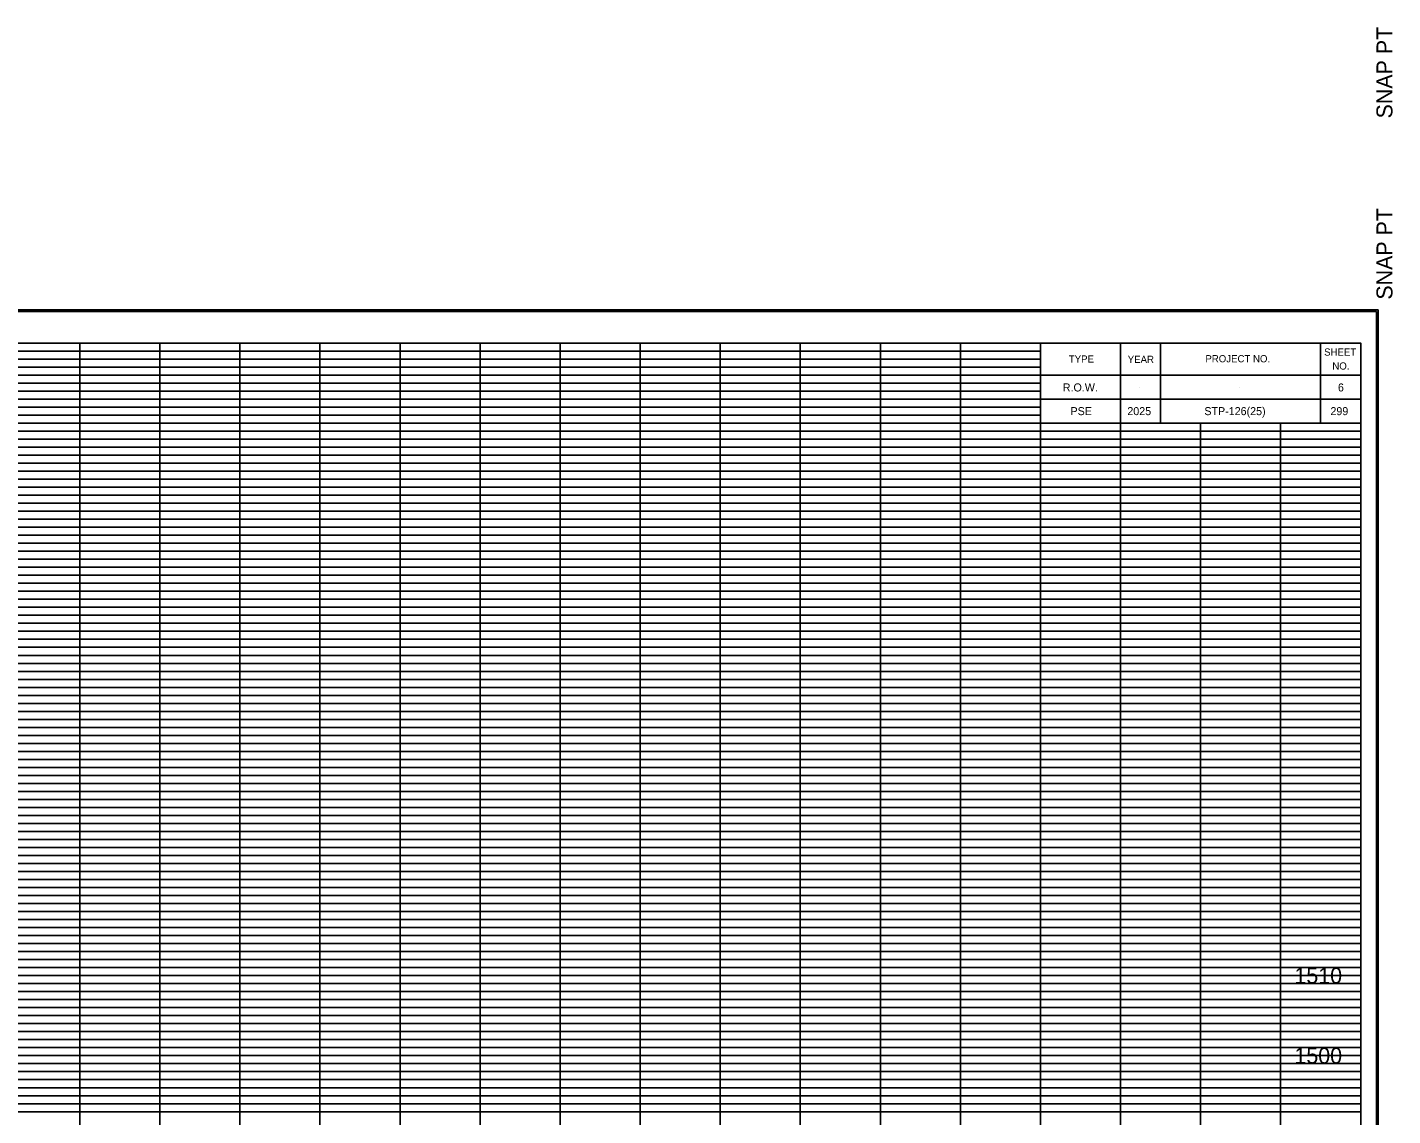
# Model space of a CAD drawing. Extents: x 980 to 2064, y 978 to 2267.
# Drawn here: x 1523.4 to 1694, y 1113.5 to 1249.4 of the extents above; entities that cross this region are included whole.
import ezdxf

# ---------------------------------------------------------------- set-up
doc = ezdxf.new("R2010")
doc.units = 0
for name, color, linetype in [('Default', 7, 'Continuous'), ('DESIGN - SCRATCH - User 1', 7, 'Continuous'), ('DESIGN - SHEET - Corner Text', 7, 'Continuous'), ('DESIGN - SHEET - Light Grid', 7, 'Continuous'), ('DESIGN - SHEET - Linework', 7, 'Continuous'), ('DESIGN - SHEET - Plot Shape', 7, 'Continuous')]:
    doc.layers.add(name, color=color, linetype=linetype)

# ---------------------------------------------------------------- blocks, each defined once
blk = doc.blocks.new('XSTSHT')
at = {"layer": 'DESIGN - SCRATCH - User 1'}
for p, q in [((28.5, 20.45), (28.5, 20.45)), ((29.24, 20.45), (29.24, 20.45)), ((30.49, 20.45), (30.49, 20.45)), ((31.74, 20.45), (31.74, 20.45)), ((28.5, 20.15), (28.5, 20.15)), ((29.24, 20.15), (29.24, 20.15)), ((30.49, 20.15), (30.49, 20.15)), ((31.74, 20.15), (31.74, 20.15))]:
    blk.add_line(p, q, dxfattribs=at)
at = {"layer": 'DESIGN - SHEET - Light Grid'}
for p, q in [((8, 20.9), (16, 20.9)), ((16, 20.9), (24, 20.9)), ((24, 20.9), (28, 20.9)), ((8, 20.8), (16, 20.8)), ((8, 20.7), (16, 20.7)), ((16, 20.8), (24, 20.8)), ((16, 20.7), (24, 20.7)), ((24, 20.8), (28, 20.8)), ((24, 20.7), (28, 20.7)), ((8, 20.6), (16, 20.6)), ((8, 20.5), (16, 20.5)), ((16, 20.6), (24, 20.6)), ((16, 20.5), (24, 20.5)), ((24, 20.6), (28, 20.6)), ((24, 20.5), (28, 20.5)), ((8, 20.4), (16, 20.4)), ((8, 20.3), (16, 20.3)), ((16, 20.4), (24, 20.4)), ((16, 20.3), (24, 20.3)), ((24, 20.4), (28, 20.4)), ((24, 20.3), (28, 20.3)), ((8, 20.2), (16, 20.2)), ((16, 20.2), (24, 20.2)), ((24, 20.2), (28, 20.2)), ((8, 20.1), (16, 20.1)), ((16, 20.1), (24, 20.1)), ((24, 20.1), (28, 20.1)), ((8, 19.9), (16, 19.9)), ((8, 19.8), (16, 19.8)), ((16, 19.9), (24, 19.9)), ((16, 19.8), (24, 19.8)), ((24, 19.9), (32, 19.9)), ((24, 19.8), (32, 19.8)), ((8, 19.7), (16, 19.7)), ((16, 19.7), (24, 19.7)), ((24, 19.7), (32, 19.7)), ((8, 19.6), (16, 19.6)), ((8, 19.5), (16, 19.5)), ((16, 19.6), (24, 19.6)), ((16, 19.5), (24, 19.5)), ((24, 19.6), (32, 19.6)), ((24, 19.5), (32, 19.5)), ((8, 19.4), (16, 19.4)), ((8, 19.3), (16, 19.3)), ((16, 19.4), (24, 19.4)), ((16, 19.3), (24, 19.3)), ((24, 19.4), (32, 19.4)), ((24, 19.3), (32, 19.3)), ((8, 19.2), (16, 19.2)), ((16, 19.2), (24, 19.2)), ((24, 19.2), (32, 19.2)), ((8, 19.1), (16, 19.1)), ((16, 19.1), (24, 19.1)), ((24, 19.1), (32, 19.1)), ((8, 18.9), (16, 18.9)), ((8, 18.8), (16, 18.8)), ((16, 18.9), (24, 18.9)), ((16, 18.8), (24, 18.8)), ((24, 18.9), (32, 18.9)), ((24, 18.8), (32, 18.8)), ((8, 18.7), (16, 18.7)), ((8, 18.6), (16, 18.6)), ((16, 18.7), (24, 18.7)), ((16, 18.6), (24, 18.6)), ((24, 18.7), (32, 18.7)), ((24, 18.6), (32, 18.6)), ((8, 18.5), (16, 18.5)), ((16, 18.5), (24, 18.5)), ((24, 18.5), (32, 18.5)), ((8, 18.4), (16, 18.4)), ((8, 18.3), (16, 18.3)), ((16, 18.4), (24, 18.4)), ((16, 18.3), (24, 18.3)), ((24, 18.4), (32, 18.4)), ((24, 18.3), (32, 18.3)), ((8, 18.2), (16, 18.2)), ((8, 18.1), (16, 18.1)), ((16, 18.2), (24, 18.2)), ((16, 18.1), (24, 18.1)), ((24, 18.2), (32, 18.2)), ((24, 18.1), (32, 18.1)), ((8, 17.9), (16, 17.9)), ((8, 17.8), (16, 17.8)), ((16, 17.9), (24, 17.9)), ((16, 17.8), (24, 17.8)), ((24, 17.9), (32, 17.9)), ((24, 17.8), (32, 17.8)), ((8, 17.7), (16, 17.7)), ((8, 17.6), (16, 17.6)), ((16, 17.7), (24, 17.7)), ((16, 17.6), (24, 17.6)), ((24, 17.7), (32, 17.7)), ((24, 17.6), (32, 17.6)), ((8, 17.5), (16, 17.5)), ((8, 17.4), (16, 17.4)), ((16, 17.5), (24, 17.5)), ((16, 17.4), (24, 17.4)), ((24, 17.5), (32, 17.5)), ((24, 17.4), (32, 17.4)), ((8, 17.3), (16, 17.3)), ((16, 17.3), (24, 17.3)), ((24, 17.3), (32, 17.3)), ((8, 17.2), (16, 17.2)), ((8, 17.1), (16, 17.1)), ((16, 17.2), (24, 17.2)), ((16, 17.1), (24, 17.1)), ((24, 17.2), (32, 17.2)), ((24, 17.1), (32, 17.1)), ((8, 16.9), (16, 16.9)), ((16, 16.9), (24, 16.9)), ((24, 16.9), (32, 16.9)), ((8, 16.8), (16, 16.8)), ((16, 16.8), (24, 16.8)), ((24, 16.8), (32, 16.8)), ((8, 16.7), (16, 16.7)), ((8, 16.6), (16, 16.6)), ((16, 16.7), (24, 16.7)), ((16, 16.6), (24, 16.6)), ((24, 16.7), (32, 16.7)), ((24, 16.6), (32, 16.6)), ((8, 16.5), (16, 16.5)), ((8, 16.4), (16, 16.4)), ((16, 16.5), (24, 16.5)), ((16, 16.4), (24, 16.4)), ((24, 16.5), (32, 16.5)), ((24, 16.4), (32, 16.4)), ((8, 16.3), (16, 16.3)), ((16, 16.3), (24, 16.3)), ((24, 16.3), (32, 16.3)), ((8, 16.2), (16, 16.2)), ((8, 16.1), (16, 16.1)), ((16, 16.2), (24, 16.2)), ((16, 16.1), (24, 16.1)), ((24, 16.2), (32, 16.2)), ((24, 16.1), (32, 16.1)), ((8, 15.9), (16, 15.9)), ((16, 15.9), (24, 15.9)), ((24, 15.9), (32, 15.9)), ((8, 15.8), (16, 15.8)), ((8, 15.7), (16, 15.7)), ((16, 15.8), (24, 15.8)), ((16, 15.7), (24, 15.7)), ((24, 15.8), (32, 15.8)), ((24, 15.7), (32, 15.7)), ((8, 15.6), (16, 15.6)), ((16, 15.6), (24, 15.6)), ((24, 15.6), (32, 15.6)), ((8, 15.5), (16, 15.5)), ((8, 15.4), (16, 15.4)), ((16, 15.5), (24, 15.5)), ((16, 15.4), (24, 15.4)), ((24, 15.5), (32, 15.5)), ((24, 15.4), (32, 15.4)), ((8, 15.3), (16, 15.3)), ((8, 15.2), (16, 15.2)), ((16, 15.3), (24, 15.3)), ((16, 15.2), (24, 15.2)), ((24, 15.3), (32, 15.3)), ((24, 15.2), (32, 15.2)), ((8, 15.1), (16, 15.1)), ((16, 15.1), (24, 15.1)), ((24, 15.1), (32, 15.1)), ((8, 14.9), (16, 14.9)), ((16, 14.9), (24, 14.9)), ((24, 14.9), (32, 14.9)), ((8, 14.8), (16, 14.8)), ((8, 14.7), (16, 14.7)), ((16, 14.8), (24, 14.8)), ((16, 14.7), (24, 14.7)), ((24, 14.8), (32, 14.8)), ((24, 14.7), (32, 14.7)), ((8, 14.6), (16, 14.6)), ((8, 14.5), (16, 14.5)), ((16, 14.6), (24, 14.6)), ((16, 14.5), (24, 14.5)), ((24, 14.6), (32, 14.6)), ((24, 14.5), (32, 14.5)), ((8, 14.4), (16, 14.4)), ((16, 14.4), (24, 14.4)), ((24, 14.4), (32, 14.4)), ((8, 14.3), (16, 14.3)), ((8, 14.2), (16, 14.2)), ((16, 14.3), (24, 14.3)), ((16, 14.2), (24, 14.2)), ((24, 14.3), (32, 14.3)), ((24, 14.2), (32, 14.2)), ((8, 14.1), (16, 14.1)), ((16, 14.1), (24, 14.1)), ((24, 14.1), (32, 14.1)), ((8, 13.9), (16, 13.9)), ((16, 13.9), (24, 13.9)), ((24, 13.9), (32, 13.9)), ((8, 13.8), (16, 13.8)), ((8, 13.7), (16, 13.7)), ((16, 13.8), (24, 13.8)), ((16, 13.7), (24, 13.7)), ((24, 13.8), (32, 13.8)), ((24, 13.7), (32, 13.7)), ((8, 13.6), (16, 13.6)), ((8, 13.5), (16, 13.5)), ((16, 13.6), (24, 13.6)), ((16, 13.5), (24, 13.5)), ((24, 13.6), (32, 13.6)), ((24, 13.5), (32, 13.5)), ((8, 13.4), (16, 13.4)), ((16, 13.4), (24, 13.4)), ((24, 13.4), (32, 13.4)), ((8, 13.3), (16, 13.3)), ((8, 13.2), (16, 13.2)), ((16, 13.3), (24, 13.3)), ((16, 13.2), (24, 13.2)), ((24, 13.3), (32, 13.3)), ((24, 13.2), (32, 13.2)), ((8, 13.1), (16, 13.1)), ((16, 13.1), (24, 13.1)), ((24, 13.1), (32, 13.1)), ((8, 12.9), (16, 12.9)), ((8, 12.8), (16, 12.8)), ((16, 12.9), (24, 12.9)), ((16, 12.8), (24, 12.8)), ((24, 12.9), (32, 12.9)), ((24, 12.8), (32, 12.8)), ((8, 12.7), (16, 12.7)), ((16, 12.7), (24, 12.7)), ((24, 12.7), (32, 12.7)), ((8, 12.6), (16, 12.6)), ((8, 12.5), (16, 12.5)), ((16, 12.6), (24, 12.6)), ((16, 12.5), (24, 12.5)), ((24, 12.6), (32, 12.6)), ((24, 12.5), (32, 12.5)), ((8, 12.4), (16, 12.4)), ((8, 12.3), (16, 12.3)), ((16, 12.4), (24, 12.4)), ((16, 12.3), (24, 12.3)), ((24, 12.4), (32, 12.4)), ((24, 12.3), (32, 12.3)), ((8, 12.2), (16, 12.2)), ((16, 12.2), (24, 12.2)), ((24, 12.2), (32, 12.2)), ((8, 12.1), (16, 12.1)), ((16, 12.1), (24, 12.1)), ((24, 12.1), (32, 12.1)), ((8, 11.9), (16, 11.9)), ((8, 11.8), (16, 11.8)), ((16, 11.9), (24, 11.9)), ((16, 11.8), (24, 11.8)), ((24, 11.9), (32, 11.9)), ((24, 11.8), (32, 11.8)), ((8, 11.7), (16, 11.7)), ((8, 11.6), (16, 11.6)), ((16, 11.7), (24, 11.7)), ((16, 11.6), (24, 11.6)), ((24, 11.7), (32, 11.7)), ((24, 11.6), (32, 11.6)), ((8, 11.5), (16, 11.5)), ((16, 11.5), (24, 11.5)), ((24, 11.5), (32, 11.5)), ((8, 11.4), (16, 11.4)), ((16, 11.4), (24, 11.4)), ((24, 11.4), (32, 11.4))]:
    blk.add_line(p, q, dxfattribs=at)
at = {"layer": 'DESIGN - SHEET - Linework'}
for p, q in [((-1.823, 21.414), (32.217, 21.414)), ((32.217, 21.414), (32.217, -0.414)), ((16, 0), (16, 21)), ((17, 0), (17, 21)), ((18, 0), (18, 21)), ((19, 0), (19, 21)), ((20, 0), (20, 21)), ((21, 0), (21, 21)), ((22, 0), (22, 21)), ((23, 0), (23, 21)), ((24, 0), (24, 21)), ((25, 0), (25, 21)), ((26, 0), (26, 21)), ((27, 0), (27, 21)), ((0, 20), (28, 20)), ((28, 0), (28, 20)), ((29, 0), (29, 20)), ((30, 0), (30, 20)), ((31, 0), (31, 20)), ((0, 19), (32, 19)), ((0, 18), (32, 18)), ((0, 17), (32, 17)), ((0, 16), (32, 16)), ((0, 15), (32, 15)), ((0, 14), (32, 14)), ((0, 13), (32, 13)), ((0, 12), (32, 12))]:
    blk.add_line(p, q, dxfattribs=at)
for points in [[(0, 21), (0, 0), (32, 0), (32, 21), (0, 21)], [(28, 21), (28, 20), (32, 20), (32, 21), (31.5, 21), (31.5, 20), (29.5, 20), (29.5, 21), (29, 21), (29, 20), (32, 20), (28, 20), (28, 20.3), (32, 20.3), (32, 20.6), (28, 20.6)]]:
    blk.add_lwpolyline(points, dxfattribs=at)
at = {"layer": 'DESIGN - SHEET - Plot Shape'}
for points in [[(-1.803, 21.394), (32.197, 21.394), (32.197, -0.394), (-1.803, -0.394)], [(-0.85, 21), (32, 21), (32, -0.25), (-0.85, -0.25)]]:
    blk.add_lwpolyline(points, close=True, dxfattribs=at)
at = {"layer": 'DESIGN - SHEET - Corner Text'}
blk.add_text('  SNAP PT', height=0.2, rotation=90, dxfattribs=at).set_placement((32.397, 21.394))
for s, p in [('TYPE', (28.354, 20.756)), ('YEAR', (29.09, 20.752)), ('PROJECT NO.', (30.06, 20.76)), ('SHEET', (31.543, 20.843)), ('NO.', (31.646, 20.669))]:
    blk.add_text(s, height=0.09, dxfattribs=at).set_placement(p)

msp = doc.modelspace()

# ---------------------------------------------------------------- block references
at = {"layer": 'Default', "xscale": 10, "yscale": 10}
msp.add_blockref('XSTSHT', (1370, 1000), dxfattribs=at)

# ---------------------------------------------------------------- texts
at = {"layer": 'Default'}
for s, p in [('     1510     ', (1678.01, 1130)), ('     1500     ', (1678.01, 1120))]:
    msp.add_text(s, height=2, dxfattribs=at).set_placement(p)
at = {"layer": 'DESIGN - SHEET - Corner Text'}
msp.add_text('SNAP PT  ', height=2, rotation=90, dxfattribs=at).set_placement((1693.97, 1238.06))
for s, p in [('R.O.W.', (1652.79, 1203.96)), ('6', (1687.16, 1203.96)), ('PSE', (1653.75, 1201)), ('2025', (1660.85, 1201)), ('STP-126(25)', (1670.47, 1201)), ('299', (1686.22, 1201))]:
    msp.add_text(s, height=1, dxfattribs=at).set_placement(p)

doc.saveas('drawing.dxf')
